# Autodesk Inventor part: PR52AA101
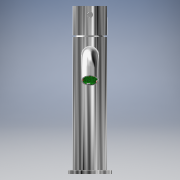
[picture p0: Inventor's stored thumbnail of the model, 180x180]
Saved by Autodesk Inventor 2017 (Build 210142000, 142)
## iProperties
Created: 2021-04
Part Number: PR52AA101
Material: Generico
Document SubType Name: Modeling
Designer: PIZZERA
Density: 1 g/cm^3
Appearance: Default
Author: PIZZERA
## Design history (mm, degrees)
feature "Base5"
node "Solido1"
node "Solido6"
